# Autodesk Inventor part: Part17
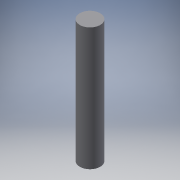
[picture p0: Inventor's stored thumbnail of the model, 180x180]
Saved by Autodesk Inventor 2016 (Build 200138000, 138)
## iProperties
Created: 2020-04
Part Number: Part17
Material: Generic
Document SubType Name: Modeling
Designer: merlin
Density: 1 g/cm^3
Appearance: Default
Author: merlin
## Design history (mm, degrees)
sketch "Sketch1"
  geometry: C1 r 1.587 at (238.125, -327.025); 1 further point
  constraints: 1 centre point
  dimensions: "d0" = 19.05 dimension on point (0, 0) C1.centre C1
extrude "Extrusion1" new body sketch "Sketch1" distance "d0" = 19.05; taper "d1" = 0 deg
body "Solid1"
